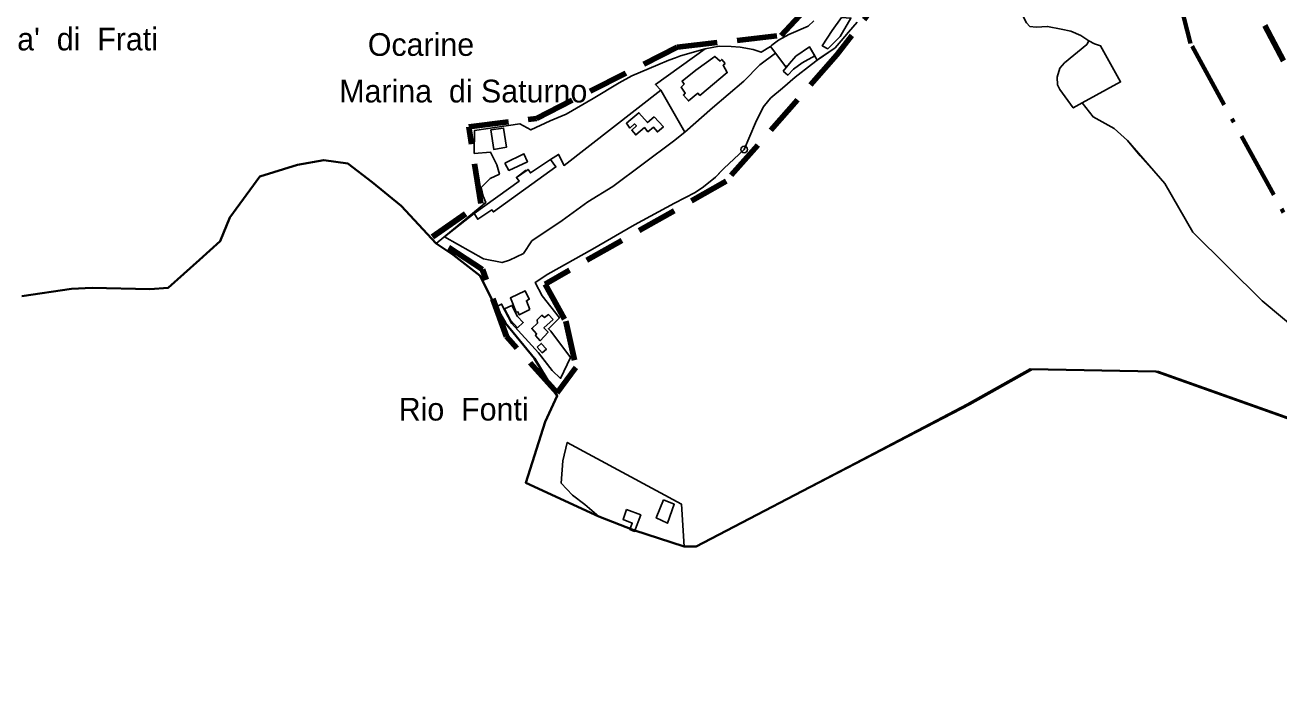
# Model space of a CAD drawing. Extents: x 645880 to 658994, y 884400 to 894744.
# Drawn here: x 657221 to 658160, y 890454 to 890956 of the extents above; entities that cross this region are included whole.
import ezdxf
from ezdxf.enums import TextEntityAlignment as Align

# ---------------------------------------------------------------- set-up
doc = ezdxf.new("R2010")
doc.units = 0
doc.header["$LTSCALE"] = 10
doc.header["$PDMODE"] = 32
doc.header["$PDSIZE"] = 5
doc.linetypes.add('DOT_DASHED', pattern=[7.7, 5, -1.2, 0.3, -1.2])
doc.linetypes.add('MEDIUM_DASHED', pattern=[4.5, 3, -1.5])
for name, color, linetype, lineweight in [('1', 7, 'Continuous', 25), ('15', 7, 'MEDIUM_DASHED', 100), ('16', 7, 'Continuous', 25), ('17', 7, 'Continuous', 25), ('45', 7, 'Continuous', 25), ('59', 7, 'Continuous', 40)]:
    doc.layers.add(name, color=color, linetype=linetype, lineweight=lineweight)
doc.layers.add('60', color=7, linetype='Continuous')

msp = doc.modelspace()

# ---------------------------------------------------------------- linework, layer by layer
at = {"layer": '1'}
msp.add_line((657697.05, 890907.11), (657714.86, 890875.6), dxfattribs=at)
for points in [[(657832.4, 890961.45), (657825.37, 890951.88), (657817.91, 890940.34), (657821.99, 890938.08), (657831.28, 890947.37), (657839.29, 890961.03)], [(657788.54, 890921.42), (657792.09, 890918.38), (657796.29, 890922.88), (657802.73, 890927.7), (657812.2, 890932.75), (657808.38, 890939.5), (657797.98, 890932.45), (657793.36, 890927.04)], [(657745.13, 890927.15), (657743.68, 890925.77), (657746.79, 890920.33), (657726.22, 890903.18), (657724.72, 890904.81), (657717.63, 890899.07), (657713.95, 890903.48), (657715.31, 890904.76), (657712.12, 890909.35), (657714.47, 890911.61), (657712.9, 890913.86), (657723.19, 890922.19), (657737.48, 890932.38), (657741.4, 890928.95), (657742.65, 890930.19)], [(657692.05, 890887.21), (657698.95, 890879.75), (657694.49, 890875.91), (657691.45, 890879.51), (657687.32, 890875.95), (657684.78, 890879.07), (657678.23, 890873.61), (657675.28, 890877.21), (657678.71, 890880.33), (657677.4, 890881.89), (657673.92, 890878.75), (657671.19, 890882.31), (657674.61, 890885.21), (657680.54, 890890.23), (657687.1, 890882.85)], [(657569.83, 890877.35), (657571.94, 890862.72), (657581.43, 890864.39), (657579.3, 890878.7)], [(657580.28, 890852.48), (657594.49, 890859.56), (657597.11, 890853.54), (657583.22, 890847.06)], [(657614.52, 890855.24), (657618.44, 890849.62), (657571.67, 890815.94), (657570.51, 890817.5), (657559.92, 890810.46), (657557.13, 890814.74), (657590.97, 890838.98), (657588.84, 890841.8), (657595.78, 890846.98), (657596.12, 890846.64), (657597.65, 890847.72), (657599.42, 890845.1)], [(657599.04, 890742.79), (657591.02, 890738.85), (657590.06, 890741.24), (657588.57, 890740.8), (657584.39, 890751.54), (657595.45, 890756.74), (657598.52, 890750.5), (657596.42, 890749.4)], [(657580, 890743.37), (657585.47, 890745.93), (657589.65, 890737.69), (657593.95, 890733.06), (657589.81, 890729.22), (657584.53, 890734.95)], [(657616.5, 890735.26), (657612.93, 890739.1), (657609.89, 890736.92), (657607.8, 890738.56), (657604.44, 890735.21), (657604.59, 890732.75), (657600.34, 890728.65), (657603.92, 890724.54), (657603.18, 890723.49), (657606.76, 890719.46), (657612.56, 890725.98), (657609.43, 890729.13)], [(657604.38, 890714.73), (657607.51, 890717.42), (657611.28, 890713.21), (657608.12, 890710.43)], [(657712.39, 890597.12), (657626.92, 890643.36), (657623.57, 890629.54), (657622.44, 890612.93), (657630.99, 890603.73), (657640.01, 890596.96), (657650.65, 890587.93), (657676.82, 890577.6), (657714.49, 890565.34)], [(657698.94, 890600.27), (657693.57, 890586.8), (657701.89, 890582.84), (657707.11, 890597.01)], [(657671.29, 890593.09), (657668.69, 890585.54), (657675.6, 890582.89), (657673.68, 890578.15), (657677.36, 890576.72), (657681.93, 890588.99)]]:
    msp.add_lwpolyline(points, close=True, dxfattribs=at)
for points in [[(657811.56, 890959.13), (657807.21, 890955.06), (657792.95, 890948.9), (657785.05, 890944.65), (657780.21, 890940.92), (657779.24, 890939.9), (657790.57, 890924.54), (657793.36, 890927.04), (657797.98, 890932.45), (657808.36, 890939.56), (657813.95, 890929.67), (657816.98, 890931.7), (657827.5, 890938.75), (657832.14, 890944.06), (657837.47, 890950.5), (657844, 890958.08)], [(657730.23, 890938.18), (657711.77, 890932.89), (657707.91, 890931.45), (657702.98, 890929.69), (657694.7, 890925.99), (657675.37, 890917.93), (657665.82, 890912.62), (657646.45, 890900.96), (657626.19, 890889.16), (657614.22, 890884.23), (657599.78, 890877.36), (657591.5, 890881.94), (657557.44, 890876.82), (657557.34, 890859.73), (657569.49, 890860.62), (657574.25, 890851.1), (657576.18, 890844.23), (657569.32, 890840.89), (657562.45, 890834.19), (657564.04, 890827.85), (657565.97, 890822.91), (657557.55, 890815.9), (657528.85, 890792.4)], [(657782.89, 890934.94), (657771.22, 890926.18), (657759.2, 890913.74), (657735.58, 890893.84), (657714.86, 890875.6), (657706.58, 890868.96), (657661, 890834.97), (657642.43, 890823.58), (657623.07, 890809.43), (657600.43, 890794.22), (657594.08, 890784.74), (657583.58, 890779.9), (657578.1, 890777.99), (657564.31, 890780.87), (657535.15, 890797.23), (657557.13, 890814.74), (657590.97, 890838.98), (657588.84, 890841.8), (657597.65, 890847.72)], [(657597.65, 890847.72), (657599.42, 890845.1), (657614.52, 890855.24), (657620.39, 890859.01), (657624.53, 890850.72), (657697.05, 890907.11), (657692.9, 890911.25), (657730.23, 890938.18)], [(657730.23, 890938.18), (657692.9, 890911.25), (657697.05, 890907.11), (657714.86, 890875.6)], [(657714.86, 890875.6), (657735.58, 890893.84), (657759.2, 890913.74), (657771.22, 890926.18), (657782.89, 890934.94), (657779.24, 890939.9)], [(657779.24, 890939.9), (657772.03, 890935.47), (657766.07, 890937.65), (657756.32, 890939.35), (657749.6, 890939.77), (657740.71, 890939.94), (657730.23, 890938.18)], [(657813.95, 890929.67), (657808.36, 890939.56), (657797.98, 890932.45), (657793.36, 890927.04), (657790.57, 890924.54), (657782.89, 890934.94)], [(657759.43, 890862.71), (657767.99, 890882.69), (657767.99, 890882.69), (657773.65, 890894.27), (657777.8, 890899.63), (657779.47, 890901.4), (657787.99, 890908.69), (657797.5, 890916.81), (657809.7, 890926.21), (657813.95, 890929.67)], [(657597.65, 890847.72), (657599.42, 890845.1), (657614.52, 890855.24), (657620.39, 890859.01), (657624.53, 890850.72), (657697.05, 890907.11)], [(657714.86, 890875.6), (657706.58, 890868.96), (657661, 890834.97), (657642.43, 890823.58), (657623.07, 890809.43), (657600.43, 890794.22), (657594.08, 890784.74), (657583.58, 890779.9), (657578.1, 890777.99), (657564.31, 890780.87), (657535.15, 890797.23), (657557.13, 890814.74), (657590.97, 890838.98), (657588.84, 890841.8), (657597.65, 890847.72)], [(657608.06, 890753.2), (657603.01, 890763.19), (657612.35, 890769.42), (657645.74, 890788.11), (657677.35, 890806.2), (657707.21, 890822.5), (657722.68, 890830.42), (657729.07, 890834.72), (657737.83, 890841.99), (657744.11, 890848.39), (657759.43, 890862.71)], [(657528.85, 890792.4), (657541.62, 890783.9), (657561.79, 890768.2), (657570.53, 890750.42), (657573.78, 890744.85), (657577.74, 890746.98), (657580.41, 890741.5)], [(657580.41, 890741.5), (657585.16, 890732.51), (657585.16, 890732.51), (657605.5, 890710.43), (657605.5, 890710.43), (657608.59, 890706.26), (657615.63, 890697.27), (657621.97, 890691.28), (657629.26, 890706.86), (657614.68, 890726.59), (657612.81, 890728.46), (657621.09, 890736.74), (657608.06, 890753.2)]]:
    msp.add_lwpolyline(points, dxfattribs=at)
msp.add_point((657759.43, 890862.71), dxfattribs=at)
at = {"layer": '15'}
for points in [[(658184.33, 890889.29), (658123.56, 891003.8)], [(657867.48, 890983.79), (657828.91, 890933.62), (657745.99, 890839.06), (657610.35, 890761.88), (657625.78, 890734.22), (657633.49, 890699.48), (657619.39, 890680.55), (657581.42, 890722.64), (657563.43, 890772.81), (657526.14, 890797.25), (657562.14, 890822.34), (657553.14, 890879.58), (657603.92, 890886.02), (657709.35, 890939.4), (657787.21, 890948.05), (657815.02, 890978.31)]]:
    msp.add_lwpolyline(points, dxfattribs=at)
at = {"layer": '16'}
for points in [[(657779.24, 890939.9), (657780.21, 890940.92), (657785.05, 890944.65), (657792.95, 890948.9), (657807.21, 890955.06), (657811.56, 890959.13)], [(657599.78, 890877.36), (657614.22, 890884.23), (657626.19, 890889.16), (657646.45, 890900.96), (657665.82, 890912.62), (657675.37, 890917.93), (657694.7, 890925.99), (657702.98, 890929.69), (657707.91, 890931.45), (657711.77, 890932.89), (657730.23, 890938.18)], [(657730.23, 890938.18), (657740.71, 890939.94), (657749.6, 890939.77), (657756.32, 890939.35), (657766.07, 890937.65), (657772.03, 890935.47), (657779.24, 890939.9)], [(657218.59, 890752.96), (657255.74, 890758.24), (657271.15, 890759.12), (657314.41, 890758.1), (657328, 890758.98), (657351.56, 890780.07), (657366.97, 890794.14), (657374.22, 890811.72), (657396.87, 890842.48), (657424.96, 890851.27), (657444.58, 890854.81), (657462.71, 890852.18), (657480.83, 890838.11), (657502.58, 890820.53), (657528.85, 890792.4), (657557.55, 890815.9), (657565.97, 890822.91), (657564.04, 890827.85), (657562.45, 890834.19), (657569.32, 890840.89), (657576.18, 890844.23), (657574.25, 890851.1), (657569.49, 890860.62), (657557.34, 890859.73), (657557.44, 890876.82), (657591.5, 890881.94), (657599.78, 890877.36)]]:
    msp.add_lwpolyline(points, dxfattribs=at)
at = {"layer": '17'}
for points in [[(657951.45, 890991.3), (657959.67, 890979.29), (657970.89, 890957.5), (657973.33, 890954.68), (657977.98, 890954.2), (657986.56, 890954.87), (657996.74, 890952.89), (658004.09, 890951.3), (658011.43, 890948.14), (658017.51, 890943.95), (658021.68, 890941.83), (658026.24, 890940.23), (658041.24, 890913.23), (658012.53, 890897.55), (658020.65, 890887.07), (658036.5, 890878.44), (658046.53, 890869.41), (658055.9, 890858.05), (658074.35, 890837.18), (658095.37, 890800.73)], [(657844, 890958.08), (657837.47, 890950.5), (657832.14, 890944.06), (657827.5, 890938.75), (657813.95, 890929.67), (657809.7, 890926.21), (657797.5, 890916.81), (657787.99, 890908.69), (657779.47, 890901.4), (657777.8, 890899.63), (657773.65, 890894.27), (657767.99, 890882.69), (657759.43, 890862.71), (657744.11, 890848.39), (657742.44, 890846.62), (657737.83, 890841.99), (657729.07, 890834.72), (657722.68, 890830.42), (657707.21, 890822.5), (657677.35, 890806.2), (657645.74, 890788.11), (657612.35, 890769.42), (657603.01, 890763.19), (657608.06, 890753.2), (657621.09, 890736.74), (657612.81, 890728.46), (657614.68, 890726.59), (657629.26, 890706.86), (657621.97, 890691.28), (657615.63, 890697.27), (657605.5, 890710.43), (657585.16, 890732.51), (657577.74, 890746.98), (657573.78, 890744.85), (657580.68, 890732.57), (657602.43, 890706.2), (657619.47, 890678.13), (657610.4, 890658.79), (657595.91, 890613.08), (657650.65, 890587.93), (657640.01, 890596.96), (657630.99, 890603.73), (657622.44, 890612.93), (657623.57, 890629.54), (657626.92, 890643.36), (657712.39, 890597.12), (657714.49, 890565.34), (657723.57, 890565.4), (657928.36, 890671.76), (657975.48, 890698.13), (658069.72, 890696.37), (658191.14, 890653.3)], [(658179.18, 890722.55), (658147.28, 890749.45), (658095.37, 890800.73), (658074.35, 890837.18), (658046.53, 890869.41), (658036.5, 890878.44), (658020.65, 890887.07), (658012.53, 890897.55), (658005.81, 890893.88), (657995.69, 890907.5), (657993.99, 890911.2), (657993.87, 890916.85), (657995.64, 890923.51), (657999.35, 890927.7), (658016, 890941.34), (658017.51, 890943.95), (658011.43, 890948.14), (658004.09, 890951.3), (657996.74, 890952.89), (657986.56, 890954.87), (657977.98, 890954.2), (657973.33, 890954.68), (657973.33, 890954.68), (657970.89, 890957.5)], [(658095.37, 890800.73), (658147.28, 890749.45), (658179.18, 890722.55), (658211.42, 890698.32), (658219.85, 890689.89), (658223.26, 890685.08), (658229.88, 890672.83), (658237.08, 890655.67), (658252.93, 890627.77), (658294.53, 890607.14), (658399.64, 890566.7), (658480.13, 890540.67), (658527.41, 890528.03), (658593.56, 890504.29), (658656.52, 890484.17)]]:
    msp.add_lwpolyline(points, dxfattribs=at)
at = {"layer": '45', "linetype": 'DOT_DASHED', "lineweight": 70}
msp.add_lwpolyline([(658508.52, 890292.72), (658293.27, 890609.33), (658193.1, 890761.3), (658093.63, 890942.11), (658032.74, 891178.84)], dxfattribs=at)
at = {"layer": '59'}
for points in [[(657676.82, 890577.6), (657650.65, 890587.93), (657595.91, 890613.08), (657610.4, 890658.79), (657619.47, 890678.13), (657602.43, 890706.2), (657580.68, 890732.57), (657570.53, 890750.42), (657561.79, 890768.2), (657541.62, 890783.9), (657528.85, 890792.4), (657502.58, 890820.53), (657480.83, 890838.11), (657462.71, 890852.18), (657444.58, 890854.81), (657424.96, 890851.27), (657396.87, 890842.48), (657374.22, 890811.72), (657366.97, 890794.14), (657351.56, 890780.07), (657328, 890758.98), (657314.41, 890758.1), (657271.15, 890759.12), (657255.74, 890758.24), (657218.59, 890752.96)], [(658189.15, 890653.36), (658067.73, 890696.43), (657973.49, 890698.19), (657926.37, 890671.82), (657843, 890627.87), (657723.57, 890565.4)], [(657723.57, 890565.4), (657714.49, 890565.34), (657676.82, 890577.6)]]:
    msp.add_lwpolyline(points, dxfattribs=at)

# ---------------------------------------------------------------- texts
at = {"layer": '60'}
for s, p in [("Ca'  di  Frati", (657259.58, 890936.89)), ('Ocarine', (657517.43, 890932.81)), ('Marina  di Saturno', (657549.11, 890897.93)), ('Rio  Fonti', (657549.39, 890659.71))]:
    msp.add_text(s, height=17, dxfattribs=at).set_placement(p, align=Align.CENTER)

doc.saveas('drawing.dxf')
